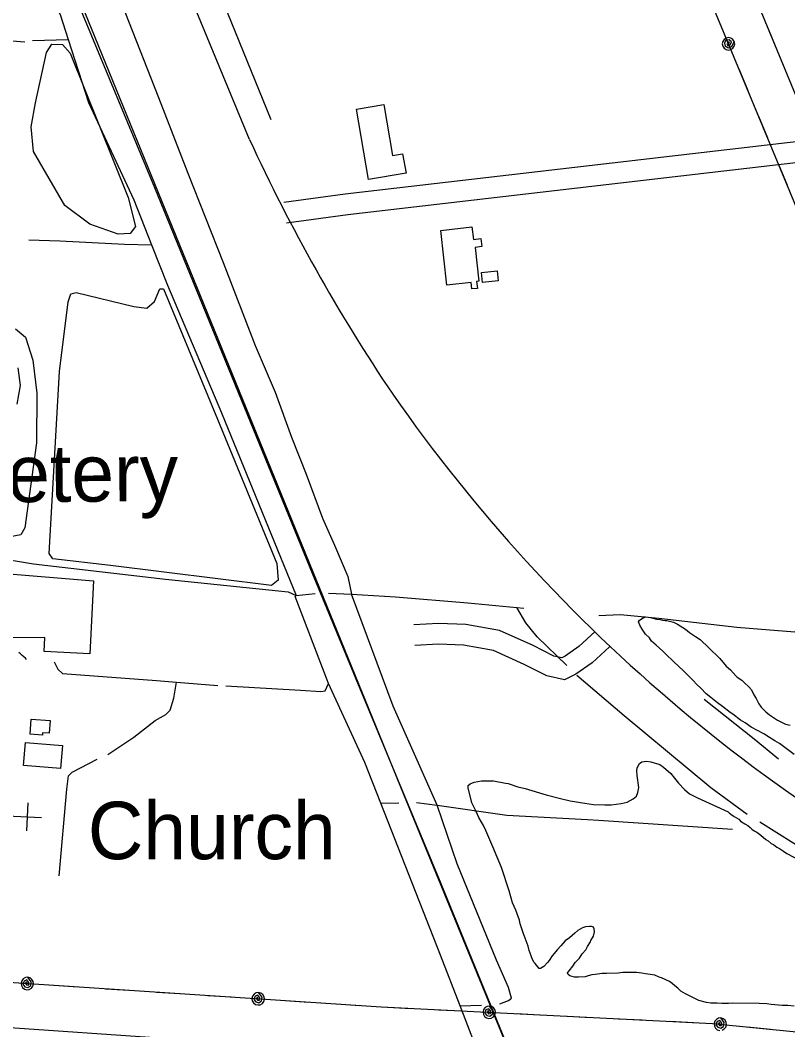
# Model space of a CAD drawing. Extents: x 3329332 to 3367211, y 631066 to 656469.
# Drawn here: x 3354799 to 3355907, y 637524 to 638982 of the extents above; entities that cross this region are included whole.
import ezdxf

# ---------------------------------------------------------------- set-up
doc = ezdxf.new("R2010")
doc.units = 0
for name, color, linetype in [('V-BLDG-OTLN', 7, 'Continuous'), ('V-RAIL-TRAK', 7, 'Continuous'), ('V-ROAD-CNTR', 7, 'Continuous'), ('V-SITE-OTLN', 7, 'Continuous'), ('V-SITE-OTLN-IDEN', 7, 'Continuous'), ('V-SITE-VEGE', 7, 'Continuous'), ('V-TOPO-SHOR', 7, 'Continuous'), ('V-UTIL-LINE', 7, 'Continuous')]:
    doc.layers.add(name, color=color, linetype=linetype)

msp = doc.modelspace()

# ---------------------------------------------------------------- linework, layer by layer
at = {"layer": 'V-BLDG-OTLN'}
for points in [[(3355302, 638751.6), (3355284.6, 638853.4), (3355324.2, 638860.2), (3355336.7, 638786.5), (3355351.3, 638789), (3355356.2, 638760.8)], [(3355415.3, 638599.2), (3355406.4, 638678.2), (3355451.4, 638683.3), (3355453.4, 638665.2), (3355464.3, 638666.4), (3355465.6, 638654.8), (3355455.9, 638653.7), (3355461.4, 638604.9), (3355458.1, 638604.5), (3355459.2, 638594.6), (3355451.1, 638593.7), (3355450, 638603.1)], [(3355465.3, 638617.7), (3355487.7, 638619.9), (3355489.1, 638605.3), (3355466.7, 638603.1)], [(3354815.3, 637972.4), (3354842.6, 637970.4), (3354841.2, 637952.2), (3354831.7, 637952.9), (3354831.4, 637949.5), (3354813.7, 637950.8)], [(3354806.8, 637938.8), (3354860.1, 637934.3), (3354857.3, 637901.2), (3354804.1, 637905.7)]]:
    msp.add_lwpolyline(points, close=True, dxfattribs=at)
at = {"layer": 'V-RAIL-TRAK'}
for points in [[(3353781.6, 641691.8), (3353874.1, 641465.8), (3353967.3, 641238.4), (3353990.1, 641184.5), (3354040.7, 641060.3), (3354097.3, 640922.6), (3354181, 640719.1), (3354196.4, 640680.2), (3354278.6, 640481.9), (3354352.8, 640301.6), (3354376.3, 640244), (3354462.2, 640033), (3354562, 639789.1), (3354667, 639534.7), (3354769.8, 639280.6), (3354779.3, 639257.1), (3354889.4, 638990.7), (3354993, 638740.1), (3355122.9, 638422.1), (3355220.5, 638183.4), (3355289.6, 638016.6)], [(3355289.6, 638016.6), (3355406.5, 637734.9), (3355531.5, 637429), (3355621.2, 637211.9)]]:
    msp.add_lwpolyline(points, dxfattribs=at)
at = {"layer": 'V-ROAD-CNTR'}
for points in [[(3355130.2, 638809.5), (3354961, 639219.6), (3354586.9, 640137.7), (3354215.3, 641035.3)], [(3355914.3, 636493.5), (3355348.7, 637874.3), (3354673.9, 639528.8)], [(3355179.6, 638719.1), (3355268.2, 638731.2), (3356209.1, 638840.2)], [(3355183.6, 638689.3), (3355272, 638701.4), (3356221, 638811.4)], [(3355629.4, 638099.1), (3355605.8, 638077.2), (3355586, 638063.3), (3355581.2, 638060.8), (3355569.5, 638063.5), (3355539.7, 638078.6), (3355491.2, 638100.3), (3355442.4, 638109.2), (3355402.9, 638110.7), (3355367.4, 638108.7)], [(3355649.8, 638077.1), (3355624.7, 638053.8), (3355601.5, 638037.5), (3355585.1, 638029.1), (3355559.2, 638035), (3355526.8, 638051.5), (3355482.3, 638071.4), (3355439.2, 638079.3), (3355403.2, 638080.7), (3355369.1, 638078.7)], [(3354808.5, 638058.6), (3354806.7, 638060.3), (3354804.5, 638062.4), (3354802.2, 638064.5), (3354799.9, 638066.6), (3354797.5, 638068.6)]]:
    msp.add_lwpolyline(points, dxfattribs=at)
for centre, radius, start, end in [((3357507.9, 639903.9), 2617.4, 204.7145, 213.9662), ((3357259.5, 639780.5), 2342.7, 214.858, 245.0374)]:
    msp.add_arc(centre, radius, start, end, dxfattribs=at)
at = {"layer": 'V-SITE-OTLN'}
for p, q in [((3354808.8, 637811.4), (3354810.8, 637851.4)), ((3354769.8, 637833.5), (3354829.8, 637830.4))]:
    msp.add_line(p, q, dxfattribs=at)
msp.add_lwpolyline([(3354638, 638194.4), (3354905.1, 638172.1), (3354900, 638066.7), (3354834.1, 638070.1), (3354835, 638090.5), (3354642.5, 638089.9), (3354614.8, 638071.3), (3354110.2, 638107.1), (3354120.6, 638231.5)], close=True, dxfattribs=at)
at = {"layer": 'V-SITE-VEGE'}
for points in [[(3354954.9, 638726), (3354965.6, 638684.1), (3354958, 638673.9), (3354940.9, 638672.6), (3354899.9, 638687.3), (3354863.7, 638714.3), (3354818.3, 638792), (3354815.2, 638827.6), (3354821.6, 638862.5), (3354837.1, 638935.1), (3354844.7, 638947.3), (3354860.5, 638946.6), (3354871.4, 638934.1)], [(3355169.9, 638197), (3355171.8, 638173), (3355162.2, 638165.5), (3354929.4, 638194.5), (3354846.6, 638204), (3354841.2, 638211.5), (3354856, 638474.5), (3354868.3, 638575.2), (3354872.5, 638586.8), (3354880, 638588.8), (3354963.5, 638568.4), (3354981.9, 638566.2), (3354993, 638575.7), (3355000.6, 638594.1), (3355006.1, 638594.1), (3355084.3, 638405.9)]]:
    msp.add_lwpolyline(points, close=True, dxfattribs=at)
for points in [[(3355916.2, 637921.4), (3355904.9, 637930.2), (3355895.1, 637937.5), (3355888.5, 637941.2), (3355880.7, 637945.9), (3355872.5, 637951.1), (3355854.5, 637961.1), (3355845.7, 637967.3), (3355839, 637971), (3355827.7, 637979.8), (3355824.1, 637981.9), (3355812.8, 637990.8), (3355805.6, 637996), (3355796.3, 638003.8), (3355789.6, 638009), (3355781.9, 638017.4), (3355775.8, 638022.6), (3355770.6, 638028.3), (3355756.2, 638042.9), (3355750.6, 638048.1), (3355741.9, 638056.4), (3355731.6, 638065.8), (3355727, 638070.4), (3355717.2, 638079.3), (3355710.5, 638085), (3355707.4, 638089.7), (3355701.8, 638095.4), (3355697.2, 638102.2), (3355693.6, 638108.4), (3355691.6, 638113.1), (3355693.1, 638115.6), (3355698.3, 638118.7), (3355702.5, 638120.2), (3355709.2, 638119.2), (3355717.9, 638117), (3355723.1, 638116.5), (3355726.2, 638115.4), (3355730.3, 638114.9), (3355732.4, 638114.9), (3355738.6, 638113.3), (3355742.2, 638112.7), (3355747.9, 638109.6), (3355759.7, 638102.3), (3355765.4, 638097.6), (3355774.1, 638091.9), (3355780.8, 638087.7), (3355793.2, 638075.2), (3355809.1, 638060.1), (3355818.3, 638049.2), (3355824.5, 638043.5), (3355832.2, 638035.1), (3355834.2, 638033.1), (3355840.9, 638028.9), (3355844.5, 638024.7), (3355851.2, 638019), (3355854.8, 638014.8), (3355858.4, 638007.6), (3355861.4, 638002.4), (3355865.5, 637994.6), (3355868.6, 637989.9), (3355875.3, 637983.2), (3355880.9, 637978.5), (3355892.3, 637971.2), (3355899, 637967.5), (3355904.1, 637965.4), (3355910.8, 637963.8)], [(3355600.5, 637621), (3355606.8, 637627.1), (3355610.4, 637633.3), (3355615.6, 637639.5), (3355618.2, 637644.1), (3355622.4, 637650.8), (3355623, 637652.9), (3355626.6, 637659.1), (3355628.2, 637665.3), (3355627.7, 637669.4), (3355626.7, 637672), (3355624.1, 637673), (3355621, 637673.1), (3355615.3, 637672.6), (3355610.7, 637671.1), (3355604.4, 637667), (3355599.8, 637663.4), (3355592, 637656.7), (3355585.7, 637652.1), (3355579.5, 637644.9), (3355574.8, 637639.8), (3355567, 637630.5), (3355562.8, 637623.8), (3355560.2, 637621.2), (3355555, 637615.1), (3355550.3, 637612.5), (3355548.3, 637612.5), (3355546.2, 637614.6), (3355542.6, 637619.8), (3355540.6, 637621.4), (3355538, 637627.6), (3355537, 637630.7), (3355533.9, 637638.5), (3355532.4, 637644.7), (3355525.3, 637663.9), (3355520.8, 637676.8), (3355519.8, 637682), (3355514.7, 637696.5), (3355510.1, 637707.4), (3355505, 637724.5), (3355493.9, 637758.1), (3355481.7, 637788.2), (3355471.5, 637811.5), (3355467.9, 637818.8), (3355461.2, 637830.2), (3355457.2, 637839), (3355451, 637851.5), (3355446, 637873.2), (3355446, 637876.8), (3355448.6, 637878.9), (3355454.3, 637881.4), (3355465.2, 637883.4), (3355482.3, 637883.3), (3355499.8, 637880.1), (3355503.4, 637879.6), (3355517.4, 637874.8), (3355528.2, 637872.2), (3355558.6, 637863.2), (3355579.3, 637857.9), (3355593.2, 637854.7), (3355614.4, 637850.9), (3355626.8, 637849.3), (3355643.3, 637848.7), (3355652.1, 637848.6), (3355666.6, 637850.6), (3355675.4, 637852.6), (3355684.2, 637857.2), (3355688.9, 637861.3), (3355691, 637866.5), (3355692.1, 637873.7), (3355689.6, 637891.3), (3355689.1, 637898), (3355689.7, 637902.2), (3355693.3, 637908.3), (3355696.5, 637910.9), (3355703.2, 637911.9), (3355709.4, 637910.8), (3355722.3, 637907.1), (3355727.9, 637902.9), (3355738.2, 637894.1), (3355743.9, 637887.3), (3355749.5, 637880.1), (3355758.2, 637870.7), (3355765.4, 637864.4), (3355776.8, 637858.7), (3355821.1, 637838.8), (3355822.6, 637837.2), (3355825.2, 637835.1), (3355829.9, 637832), (3355836.5, 637827.8), (3355839.1, 637825.2), (3355845.3, 637821.5), (3355849.4, 637818.9), (3355853, 637815.8), (3355855.1, 637813.7), (3355858.7, 637811.1), (3355862.3, 637809), (3355868.5, 637804.9), (3355875.6, 637798.6), (3355878.7, 637796.5), (3355883.4, 637792.9)], [(3355883.4, 637792.9), (3355886.5, 637791.3), (3355891.6, 637787.6), (3355895.2, 637785.6), (3355900.9, 637781.9), (3355906, 637778.3), (3355915.8, 637773), (3355923, 637769.4), (3355934.4, 637762.6), (3355942.6, 637758.4), (3355954.4, 637751.6), (3355958, 637749.5), (3355968.3, 637743.2), (3355974, 637739), (3355983.3, 637733.8), (3355986.4, 637731.7), (3355999.2, 637724.4)], [(3355916.5, 637558), (3355907.2, 637559.1), (3355898.9, 637559.1), (3355883.4, 637560.2), (3355877.2, 637561.3), (3355865.9, 637561.9), (3355827.1, 637562.2), (3355821.4, 637561.7), (3355812.1, 637561.7), (3355805.4, 637562.3), (3355796.1, 637562.3), (3355789.9, 637563.4), (3355779, 637566.1), (3355759.5, 637576), (3355752.8, 637579.7), (3355748.7, 637583.8), (3355744, 637587.5), (3355740.4, 637590.6), (3355736.3, 637593.7), (3355725, 637599), (3355721.4, 637600), (3355715.2, 637602.7), (3355701.7, 637604.8), (3355696.6, 637605.4), (3355688.8, 637606.5), (3355669.2, 637606.6), (3355662.5, 637605.6), (3355645.4, 637605.2), (3355639.2, 637605.2), (3355629.4, 637603.7), (3355624.2, 637603.3), (3355619, 637601.7), (3355614.9, 637600.2), (3355605, 637599.8), (3355599.4, 637599.8), (3355592.6, 637601.9), (3355590.1, 637603.5), (3355589.1, 637606.1), (3355591.7, 637609.1), (3355596.9, 637615.8), (3355600.5, 637621)]]:
    msp.add_lwpolyline(points, dxfattribs=at)
at = {"layer": 'V-TOPO-SHOR'}
for p, q in [((3354817, 638952.7), (3354868.4, 638954)), ((3355634.3, 638122.2), (3355665.5, 638123.5)), ((3355319.6, 637851.2), (3355345.9, 637851.7)), ((3355371.5, 637852.2), (3355401.1, 637848.3)), ((3355866.9, 637824.2), (3356015.2, 637730.7)), ((3355434.2, 637558.3), (3355465.3, 637559.4))]:
    msp.add_line(p, q, dxfattribs=at)
for points in [[(3355161.6, 638837.9), (3355093.2, 639005.9), (3355028.6, 639156.8)], [(3354876.6, 639054.8), (3354899.8, 639060.8), (3354902.1, 639059.3), (3354914.4, 639050.7), (3354927.4, 639038.3), (3354950.3, 638994.1), (3354998.9, 638870.3), (3355041.4, 638761.1), (3355092.2, 638631.9), (3355138.5, 638511.9), (3355167.4, 638444.5), (3355190.9, 638379.5), (3355212.1, 638326.1), (3355235.6, 638262.7), (3355253.1, 638223.9), (3355272.1, 638178.3), (3355277.4, 638152.7)], [(3354827.8, 639039.7), (3354840.1, 639022.6), (3354856.8, 638990.1), (3354868.4, 638954), (3354897.7, 638863.2), (3354963.1, 638722.3), (3354988.7, 638657.4), (3355011.7, 638599.2), (3355090, 638415), (3355197.8, 638151)], [(3354181.8, 638980.9), (3354269.1, 638977.2), (3354306.1, 638974.6), (3354323.8, 638973), (3354354.7, 638969.7), (3354372.4, 638967.2), (3354389.4, 638971), (3354421.1, 638971.6), (3354483.6, 638969.6), (3354532.2, 638964.6), (3354609.4, 638964.1), (3354691.2, 638959.7), (3354806.2, 638950.4)], [(3354811.7, 638664.8), (3354856.4, 638663), (3354949.8, 638658.5), (3354988.7, 638657.4)], [(3354792.3, 638536), (3354806.9, 638524.3), (3354817.5, 638491.1), (3354823.3, 638443.2), (3354822.8, 638371.4), (3354805.8, 638248.7), (3354800.3, 638238.7), (3354784.9, 638235.8)], [(3354794.7, 638427.1), (3354799.5, 638454.1), (3354796.5, 638479.6)], [(3354171.8, 638255.1), (3354258.2, 638243.7), (3354441.8, 638228.6), (3354606.9, 638212.8), (3354759.7, 638206.4), (3354818.3, 638196.8), (3355008.9, 638174.6), (3355186.3, 638156.5), (3355197.8, 638151)], [(3355244.1, 638024.1), (3355196.3, 638149.4), (3355197.8, 638151), (3355224.9, 638153.9)], [(3355244.2, 638154.5), (3355277.4, 638152.7), (3355341, 638149.3), (3355445.3, 638140.2), (3355516.3, 638133.7), (3355526.1, 638132.8)], [(3355401.1, 637848.3), (3355337.8, 637991.2), (3355277.4, 638152.7)], [(3355588.1, 638050.1), (3355545.6, 638091.5), (3355529, 638111.5), (3355516.3, 638133.7)], [(3355665.5, 638123.5), (3355721.1, 638118.5), (3355833.7, 638105.4), (3355881.5, 638101.2)], [(3355881.5, 638101.2), (3356086.3, 638084.9), (3356473.6, 638052.6)], [(3354848.2, 638055.1), (3354853.6, 638044.7), (3354860.5, 638038.4), (3354996, 638028.4), (3355024.9, 638026), (3355084.5, 638020.9)], [(3355602.5, 638036.1), (3355671.2, 637977.5), (3355796.3, 637873.6), (3355848.6, 637835.2)], [(3354925.9, 637921.3), (3354963.4, 637946.6), (3354994, 637970.6), (3355009.3, 637979.4), (3355015.6, 637985.6), (3355021.2, 638002.9), (3355024.9, 638026)], [(3355096.2, 638020.8), (3355204.1, 638014.5), (3355233.1, 638012.2), (3355239.3, 638013.5), (3355244.1, 638024.1)], [(3355657.2, 637013.6), (3355577, 637205.1), (3355566.6, 637230.2), (3355484.6, 637427.8), (3355434.2, 637558.3), (3355405.9, 637631.7), (3355319.6, 637851.2), (3355296.5, 637909.8), (3355244.1, 638024.1)], [(3355786.5, 638001.3), (3355858.5, 637943.8), (3355893.8, 637915)], [(3354855.4, 637746.1), (3354866.7, 637871.2), (3354868.9, 637890.5), (3354874.5, 637896), (3354910.6, 637914.5)], [(3355491.6, 637561.3), (3355504.1, 637566.1), (3355508.3, 637569.5), (3355504.3, 637584.7), (3355486.6, 637624.3), (3355430.2, 637763.7), (3355401.1, 637848.3), (3355501.9, 637833.7), (3355618.1, 637827.3), (3355634, 637826.5), (3355827.5, 637813.4)]]:
    msp.add_lwpolyline(points, dxfattribs=at)
at = {"layer": 'V-UTIL-LINE'}
for points in [[(3356375, 637770.1), (3355057, 640957.9)], [(3356319.9, 637747.2), (3354997, 640934.2)], [(3355892.8, 638936.3), (3355879.8, 638967.7)], [(3355821.6, 638947.6), (3355823.2, 638950), (3355820.9, 638949.9), (3355819.5, 638947.6), (3355820.9, 638945), (3355824.1, 638946.2), (3355826, 638950.5), (3355822.8, 638953.4), (3355818, 638952.8), (3355816, 638948.6), (3355816.8, 638944.2), (3355821.1, 638942), (3355826.3, 638943.8), (3355830, 638951.1), (3355828, 638954), (3355825.1, 638955.9), (3355821.6, 638956.6), (3355818.2, 638955.9), (3355815.3, 638954), (3355813.3, 638951.1), (3355812.6, 638947.6), (3355813.3, 638944.2), (3355815.3, 638941.2), (3355818.2, 638939.3), (3355821.7, 638938.6), (3355825.1, 638939.3), (3355828, 638941.3), (3355830, 638944.2), (3355830.6, 638947.6), (3355830, 638951.1)], [(3355836.6, 638911.6), (3355849.6, 638880.2)], [(3355865, 638843.2), (3355878, 638811.8)], [(3355893.3, 638774.9), (3355906.4, 638743.5)], [(3353663.1, 637666.6), (3355320.2, 637556.9), (3355798.7, 637533.1), (3356171.8, 637495.8)], [(3355570.4, 637248.4), (3355540, 637235.6), (3355440, 637481.9), (3355083.9, 637505.8), (3354693.4, 637532.7), (3354283.6, 637559.8), (3353837.4, 637589.9), (3353651.5, 637603.1), (3353647, 637603.6), (3353574.8, 637607.6), (3353571.3, 637609)], [(3354809.6, 637590.7), (3354808.1, 637593.2), (3354807.1, 637591.1), (3354808.6, 637588.7), (3354811.5, 637588.9), (3354811.9, 637592.2), (3354808.9, 637595.8), (3354804.9, 637594.3), (3354803.3, 637589.7), (3354806.2, 637586.1), (3354810.4, 637584.9), (3354814.4, 637587.7), (3354815, 637593.2), (3354810.2, 637599.7), (3354806.7, 637599.2), (3354803.6, 637597.5), (3354801.5, 637594.7), (3354800.6, 637591.3), (3354801, 637587.8), (3354802.8, 637584.8), (3354805.6, 637582.6), (3354809, 637581.7), (3354812.4, 637582.2), (3354815.5, 637583.9), (3354817.6, 637586.7), (3354818.5, 637590.1), (3354818.1, 637593.6), (3354816.3, 637596.6), (3354813.5, 637598.8), (3354810.2, 637599.7)], [(3354848.5, 637588.1), (3354882.4, 637585.9)], [(3354922.3, 637583.2), (3354956.2, 637581)], [(3354996.2, 637578.4), (3355030.1, 637576.1)], [(3355142.8, 637568.6), (3355141.3, 637571.1), (3355140.4, 637569), (3355141.9, 637566.7), (3355144.8, 637566.8), (3355145.2, 637570.2), (3355142.2, 637573.8), (3355138.2, 637572.3), (3355136.6, 637567.7), (3355139.4, 637564.1), (3355143.7, 637562.8), (3355147.6, 637565.6), (3355148.3, 637571.1), (3355143.4, 637577.6), (3355139.9, 637577.2), (3355136.9, 637575.4), (3355134.8, 637572.6), (3355133.8, 637569.2), (3355134.3, 637565.8), (3355136.1, 637562.7), (3355138.8, 637560.6), (3355142.2, 637559.7), (3355145.7, 637560.1), (3355148.8, 637561.9), (3355150.9, 637564.7), (3355151.8, 637568.1), (3355151.4, 637571.5), (3355149.6, 637574.6), (3355146.8, 637576.7), (3355143.4, 637577.6)], [(3355070, 637573.5), (3355103.9, 637571.2)], [(3355181.8, 637566.1), (3355215.7, 637563.8)], [(3355255.6, 637561.2), (3355289.5, 637558.9)], [(3355329.4, 637556.4), (3355363.4, 637554.7)], [(3355403.3, 637552.8), (3355437.3, 637551.1)], [(3355476.2, 637549.1), (3355474.7, 637551.6), (3355473.8, 637549.4), (3355475.3, 637547.1), (3355478.2, 637547.3), (3355478.6, 637550.7), (3355475.5, 637554.2), (3355471.5, 637552.7), (3355470, 637548), (3355472.9, 637544.5), (3355477.2, 637543.3), (3355481.1, 637546.2), (3355481.7, 637551.7), (3355476.7, 637558.1), (3355473.2, 637557.6), (3355470.2, 637555.8), (3355468.1, 637553), (3355467.3, 637549.6), (3355467.8, 637546.1), (3355469.6, 637543.1), (3355472.4, 637541), (3355475.8, 637540.1), (3355479.3, 637540.6), (3355482.3, 637542.5), (3355484.4, 637545.3), (3355485.2, 637548.7), (3355484.7, 637552.2), (3355482.9, 637555.2), (3355480.1, 637557.3), (3355476.7, 637558.1)], [(3355515.2, 637547.2), (3355549.2, 637545.5)], [(3355589.1, 637543.5), (3355623.1, 637541.8)], [(3355663, 637539.8), (3355697, 637538.1)], [(3355736.9, 637536.1), (3355770.9, 637534.4)], [(3355809.8, 637531.9), (3355808.4, 637534.5), (3355807.4, 637532.4), (3355808.8, 637530), (3355811.7, 637530), (3355812.2, 637533.4), (3355809.3, 637537.1), (3355805.3, 637535.7), (3355803.5, 637531.2), (3355806.2, 637527.5), (3355810.5, 637526.1), (3355814.5, 637528.8), (3355815.4, 637534.2), (3355810.7, 637540.9), (3355807.2, 637540.6), (3355804.1, 637538.9), (3355801.9, 637536.2), (3355800.8, 637532.8), (3355801.2, 637529.3), (3355802.8, 637526.2), (3355805.5, 637524), (3355808.9, 637523)], [(3355812.4, 637523.3), (3355815.5, 637525), (3355817.7, 637527.7), (3355818.7, 637531), (3355818.4, 637534.5), (3355816.8, 637537.6), (3355814, 637539.9), (3355810.7, 637540.9)], [(3355848.6, 637528.1), (3355882.4, 637524.7)]]:
    msp.add_lwpolyline(points, dxfattribs=at)

# ---------------------------------------------------------------- texts
at = {"layer": 'V-SITE-OTLN-IDEN'}
msp.add_text('Cemetery', height=83, rotation=0.3915, dxfattribs=at).set_placement((3354546.4, 638284.1))
msp.add_text('Church', height=83, dxfattribs=at).set_placement((3354896.9, 637770.2))

doc.saveas('drawing.dxf')
